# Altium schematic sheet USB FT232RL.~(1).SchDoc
size A4
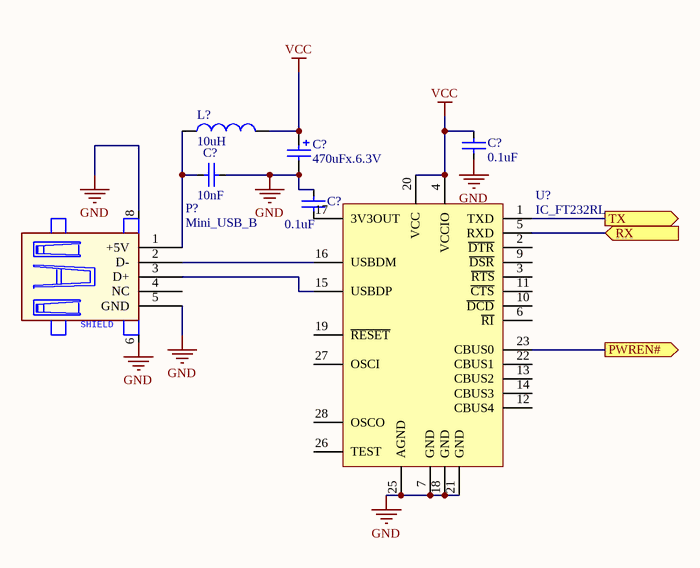
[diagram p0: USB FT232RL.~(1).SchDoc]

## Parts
(Parts that share a designator on the sheet are numbered #1, #2 ... from top to bottom, then left to right.)
C?#1  0.1uF  [C0805\2P]
C?#2  470uFx.6.3V  [CaseD_EIA7343]
C?#3  10nF  [C0805\2P]
C?#4  0.1uF  [C0805\2P]
L?  10uH  [LL0805\2P]
P?  Mini_USB_B  [4UCON_MINI_USB-B]
U?  IC_FT232RL  [SSOP-28]

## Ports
PWREN# (out), RX (in), TX (out)

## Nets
GND: C?#1.2 C?#2.2 C?#3.2 C?#4.1 P?.5(GND) P?.6(GND) P?.8(GND) U?.7(GND) U?.18(GND) U?.21(GND) U?.25(AGND)
NC: U?.8(NC) U?.24(NC)
VCC: C?#1.1 C?#2.1 L?.2 U?.4(VCCIO) U?.20(VCC)
PWREN#: U?.23(CBUS0) ; port PWREN#
RX: U?.5(RXD) ; port RX
TX: U?.1(TXD) ; port TX
NetC?#3_1: C?#3.1 L?.1 P?.1(+5V)
NetC?#4_2: C?#4.2 U?.17(3V3OUT)
NetP?_2: P?.2(D-) U?.16(USBDM)
NetP?_3: P?.3(D+) U?.15(USBDP)

Not connected (* = marked no-connect by the designer): P? 4(NC); U? 2(~{DTR}) 3(~{RTS}) 6(~{RI}) 9(~{DSR}) 10(~{DCD}) 11(~{CTS}) 12(CBUS4) 13(CBUS2) 14(CBUS3) 19(~{RESET}) 22(CBUS1) 26(TEST) 27(OSCI) 28(OSCO)

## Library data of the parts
C?#1 C?#3 C?#4 = Cap_Cer: Capacitor ceramic
C?#2 = Cap_Tan: Tantal capacitor
L? = Inductor
U? = IC_FT232RL: FT232R USB UART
